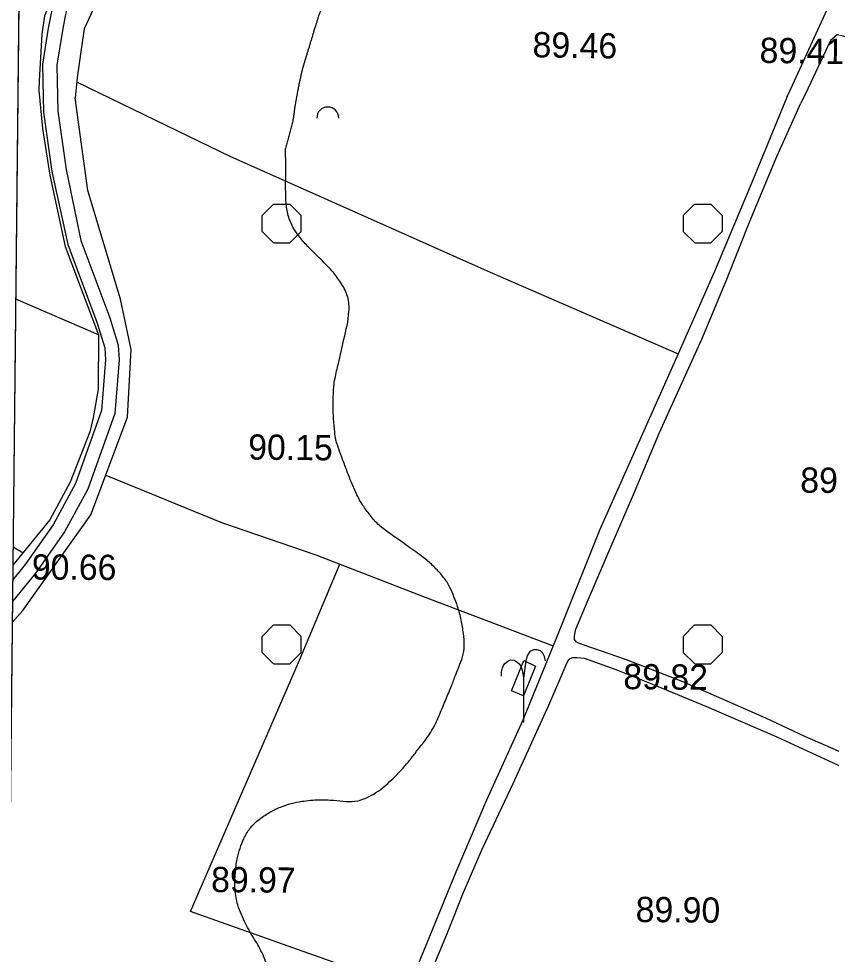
# Model space of a CAD drawing. Extents: x 417995 to 421451, y 4454518 to 4458015.
# Drawn here: x 419147.2 to 419340.2, y 4455617.9 to 4455840.2 of the extents above; entities that cross this region are included whole.
import ezdxf

# ---------------------------------------------------------------- set-up
doc = ezdxf.new("R2010")
doc.units = 0
for name, color, linetype in [('Egri_1m', 7, 'Continuous'), ('Hid_Havuz', 7, 'Continuous'), ('PAFTALAMA', 7, 'Continuous'), ('PL_KA_TARIM_ALANI', 7, 'Continuous'), ('S_Meyvalik', 7, 'Continuous'), ('Sinir_Duvar_tek_tarafa_ait', 7, 'Continuous'), ('Sinir_itirazli_Mulkiyet', 7, 'Continuous'), ('Sinir_Tel_bir_taraf', 7, 'Continuous'), ('TR_TARIMALANI', 7, 'Continuous'), ('Y_Kot_Noktasi', 7, 'Continuous'), ('Y_Lejant', 7, 'Continuous'), ('Y_Yol_Kotu', 7, 'Continuous'), ('Yol_Sose', 7, 'Continuous'), ('Yol_Toprak_Duz', 7, 'Continuous'), ('Yol_Toprak_Kesik', 7, 'Continuous')]:
    doc.layers.add(name, color=color, linetype=linetype)

msp = doc.modelspace()

# ---------------------------------------------------------------- linework, layer by layer
at = {"layer": 'Egri_1m'}
for points in [[(419266.78, 4455981.27), (419267.42, 4455981), (419268.7, 4455980.26), (419269.84, 4455979.15), (419271.04, 4455977.2), (419271.89, 4455975.31), (419272.51, 4455973.1), (419272.92, 4455970.46), (419273.07, 4455966.57), (419273.12, 4455960.67), (419273.1, 4455954.88), (419273.05, 4455949.5), (419272.97, 4455944.17), (419272.8, 4455940.5), (419272.47, 4455936.84), (419272.13, 4455934.62), (419271.58, 4455932.71), (419270.21, 4455929.62), (419268.24, 4455926.08), (419266.21, 4455923.01), (419264.28, 4455920.31), (419262.23, 4455917.43), (419259.91, 4455914.11), (419257.55, 4455910.82), (419255.12, 4455907.57), (419252.68, 4455904.32), (419250.66, 4455901.62), (419248.66, 4455898.95), (419245.71, 4455894.85), (419242.59, 4455890.24), (419240.4, 4455886.68), (419238.97, 4455883.75), (419237.74, 4455880.42), (419236.58, 4455876.62), (419235.26, 4455872.41), (419233.29, 4455866.97), (419231.01, 4455861.74), (419228.78, 4455857.75), (419226.38, 4455853.86), (419223.46, 4455849.44), (419220.52, 4455844.92), (419219.37, 4455843.07), (419218.99, 4455842.3), (419218.72, 4455841.65), (419218.52, 4455841.14), (419218.32, 4455840.54), (419218.09, 4455839.78), (419217.84, 4455838.99), (419217.54, 4455838), (419217.24, 4455837.02)], [(419217.24, 4455837.02), (419217.12, 4455836.62), (419216.99, 4455836.22), (419216.87, 4455835.83), (419216.75, 4455835.43), (419216.63, 4455835.03), (419216.51, 4455834.64), (419216.38, 4455834.24), (419216.26, 4455833.84), (419216.14, 4455833.44), (419216.02, 4455833.05), (419215.89, 4455832.65), (419215.77, 4455832.25), (419215.65, 4455831.85), (419215.53, 4455831.46), (419215.41, 4455831.06), (419215.28, 4455830.66), (419215.16, 4455830.27), (419215.04, 4455829.87), (419214.92, 4455829.47), (419214.82, 4455829.16), (419214.77, 4455828.96), (419214.72, 4455828.77), (419214.67, 4455828.58), (419214.62, 4455828.38), (419214.56, 4455828.19), (419214.51, 4455827.99), (419214.46, 4455827.8), (419214.41, 4455827.61), (419214.36, 4455827.41), (419214.31, 4455827.22), (419214.27, 4455827.02), (419214.23, 4455826.83), (419214.18, 4455826.63), (419214.14, 4455826.44), (419214.1, 4455826.24), (419214.06, 4455826.04), (419214.01, 4455825.85), (419213.97, 4455825.65), (419213.93, 4455825.46), (419213.91, 4455825.36), (419213.89, 4455825.3), (419213.88, 4455825.23), (419213.87, 4455825.17), (419213.85, 4455825.1), (419213.84, 4455825.03), (419213.83, 4455824.97), (419213.81, 4455824.9), (419213.8, 4455824.83), (419213.79, 4455824.77)], [(419213.79, 4455824.77), (419213.75, 4455824.58), (419213.71, 4455824.39), (419213.68, 4455824.21), (419213.64, 4455824.02), (419213.6, 4455823.83), (419213.57, 4455823.64), (419213.53, 4455823.46), (419213.49, 4455823.27), (419213.46, 4455823.08), (419213.42, 4455822.89), (419213.38, 4455822.69), (419213.32, 4455822.36), (419213.26, 4455822.03), (419213.2, 4455821.7), (419213.14, 4455821.37), (419213.08, 4455821.04), (419213.02, 4455820.71), (419212.96, 4455820.37), (419212.9, 4455820.04), (419212.84, 4455819.71), (419212.78, 4455819.38), (419212.73, 4455819.07), (419212.7, 4455818.84), (419212.67, 4455818.62), (419212.64, 4455818.39), (419212.62, 4455818.16), (419212.59, 4455817.93), (419212.56, 4455817.71), (419212.53, 4455817.48), (419212.5, 4455817.25), (419212.47, 4455817.02), (419212.45, 4455816.8), (419212.42, 4455816.59), (419212.38, 4455816.43), (419212.35, 4455816.28), (419212.32, 4455816.12), (419212.29, 4455815.96), (419212.26, 4455815.8), (419212.12, 4455815.26), (419211.96, 4455814.67), (419211.81, 4455814.07), (419211.66, 4455813.48), (419211.5, 4455812.89), (419211.35, 4455812.3), (419211.2, 4455811.7), (419211.04, 4455811.11), (419210.89, 4455810.52), (419210.74, 4455809.93), (419210.58, 4455809.34)], [(419244.73, 4455670.16), (419245.9, 4455672.13), (419247.18, 4455674.97), (419248.62, 4455678.37), (419249.98, 4455681.7), (419250.97, 4455684.25), (419251.74, 4455686.2), (419252.57, 4455688.55), (419253.01, 4455691.2), (419252.79, 4455694.14), (419252.28, 4455697.3), (419251.4, 4455700.53), (419250.55, 4455702.85), (419249.6, 4455705.05), (419248.11, 4455707.42), (419246.01, 4455709.76), (419243.82, 4455711.77), (419241.92, 4455713.18), (419238.31, 4455715.77), (419235.11, 4455718.04), (419232.5, 4455720.1), (419230.4, 4455722.53), (419228.72, 4455724.85), (419227.15, 4455727.82), (419225.94, 4455730.67), (419224.8, 4455733.62), (419223.71, 4455736.57), (419222.87, 4455738.93), (419222.54, 4455740.05), (419222.17, 4455742.75), (419221.93, 4455745.84), (419221.86, 4455748.94), (419221.95, 4455751.68), (419222.02, 4455752.71), (419222.32, 4455754.76), (419223.1, 4455758.24), (419224.41, 4455764), (419225.62, 4455770.61), (419225.34, 4455774.02), (419223.85, 4455777.19), (419221.92, 4455779.86), (419218.91, 4455783), (419215.78, 4455786.13), (419213.68, 4455788.57), (419211.43, 4455792.64), (419210.78, 4455795.75), (419210.61, 4455798.4), (419210.59, 4455801.07), (419210.6, 4455804.42), (419210.58, 4455809.34)], [(419243.78, 4455668.85), (419243.76, 4455668.82), (419243.74, 4455668.79), (419243.72, 4455668.77), (419243.7, 4455668.74), (419243.68, 4455668.72), (419243.66, 4455668.69), (419243.64, 4455668.66), (419243.62, 4455668.64), (419243.6, 4455668.61), (419243.58, 4455668.58), (419243.56, 4455668.56), (419243.54, 4455668.53), (419243.52, 4455668.5), (419243.5, 4455668.48), (419243.48, 4455668.45), (419243.46, 4455668.43), (419243.44, 4455668.4), (419243.42, 4455668.37), (419243.4, 4455668.35), (419243.38, 4455668.32), (419243.36, 4455668.29), (419243.34, 4455668.27), (419243.32, 4455668.24), (419243.3, 4455668.21), (419243.28, 4455668.19), (419243.26, 4455668.16), (419243.24, 4455668.14), (419243.22, 4455668.11), (419243.2, 4455668.08), (419243.18, 4455668.06), (419243.16, 4455668.03), (419243.14, 4455668), (419243.12, 4455667.98), (419243.1, 4455667.95), (419243.08, 4455667.92), (419243.06, 4455667.9), (419243.04, 4455667.87), (419243.02, 4455667.85), (419243, 4455667.82), (419242.98, 4455667.79), (419242.96, 4455667.77), (419242.94, 4455667.74), (419242.92, 4455667.71), (419242.9, 4455667.69), (419242.88, 4455667.66), (419242.86, 4455667.63), (419242.84, 4455667.61), (419242.82, 4455667.58), (419242.8, 4455667.56)], [(419243.78, 4455668.85), (419243.8, 4455668.87), (419243.82, 4455668.9), (419243.84, 4455668.93), (419243.86, 4455668.95), (419243.88, 4455668.98), (419243.9, 4455669.01), (419243.92, 4455669.03), (419243.93, 4455669.06), (419243.95, 4455669.09), (419243.97, 4455669.12), (419243.99, 4455669.14), (419244.01, 4455669.17), (419244.03, 4455669.2), (419244.05, 4455669.22), (419244.07, 4455669.25), (419244.09, 4455669.28), (419244.11, 4455669.3), (419244.13, 4455669.33), (419244.15, 4455669.36), (419244.17, 4455669.38), (419244.19, 4455669.41), (419244.21, 4455669.44), (419244.23, 4455669.46), (419244.25, 4455669.49), (419244.27, 4455669.52), (419244.28, 4455669.54), (419244.3, 4455669.57), (419244.32, 4455669.6), (419244.34, 4455669.62), (419244.36, 4455669.65), (419244.38, 4455669.68), (419244.4, 4455669.7), (419244.42, 4455669.73), (419244.44, 4455669.76), (419244.46, 4455669.78), (419244.48, 4455669.81), (419244.5, 4455669.84), (419244.52, 4455669.86), (419244.54, 4455669.89), (419244.56, 4455669.92), (419244.58, 4455669.95), (419244.6, 4455669.97), (419244.61, 4455670), (419244.63, 4455670.03), (419244.65, 4455670.05), (419244.67, 4455670.08), (419244.69, 4455670.11), (419244.71, 4455670.13), (419244.73, 4455670.16)], [(419230.59, 4455588.25), (419228.85, 4455588.77), (419226.6, 4455589.19), (419223.72, 4455589.67), (419220.1, 4455590.29), (419217.36, 4455591.45), (419215.16, 4455592.75), (419213.01, 4455594.48), (419210.83, 4455597.01), (419209.58, 4455599.31), (419208.45, 4455601.64), (419207.57, 4455603.92), (419207.07, 4455606.1), (419206.81, 4455608.27), (419206.68, 4455609.83), (419206.51, 4455611.6), (419206.24, 4455613.84), (419205.95, 4455615.6), (419205.22, 4455617.75), (419204.2, 4455619.72), (419203.21, 4455621.44), (419202.07, 4455623.33), (419201.08, 4455625.19), (419200.12, 4455627.31), (419199.23, 4455629.62), (419198.82, 4455631.4), (419198.58, 4455633.32), (419198.53, 4455635.21), (419198.65, 4455637.31), (419199.08, 4455640.53), (419199.75, 4455643.06), (419200.65, 4455645.39), (419202.04, 4455647.67), (419204.42, 4455650.03), (419206.87, 4455651.64), (419209.38, 4455652.86), (419211.93, 4455653.7), (419214.46, 4455654.23), (419218.57, 4455654.6), (419221.99, 4455654.47), (419224.86, 4455654.2), (419227.75, 4455654.38), (419230.41, 4455655.37), (419232.56, 4455656.64), (419234.36, 4455658.08), (419236.17, 4455659.76), (419238.03, 4455661.65), (419239.74, 4455663.63), (419241.31, 4455665.63), (419242.8, 4455667.56)]]:
    msp.add_spline(points, degree=3, dxfattribs=at)
at = {"layer": 'Hid_Havuz'}
for points in [[(419272.32, 4455687.59), (419272.07, 4455688.64), (419271.69, 4455689.41), (419271.13, 4455689.97), (419270.25, 4455690.21), (419269.41, 4455690.21), (419268.61, 4455689.83), (419268.05, 4455688.99), (419267.59, 4455687.66), (419267.07, 4455683.46)], [(419261.82, 4455683.95), (419261.85, 4455684.96), (419262.06, 4455685.91), (419262.34, 4455686.5), (419262.66, 4455686.96), (419263.32, 4455687.52), (419264.02, 4455687.83), (419264.76, 4455687.73), (419265.46, 4455687.41), (419266.02, 4455686.89), (419266.47, 4455686.33), (419266.75, 4455685.42), (419266.89, 4455684.61), (419267.07, 4455683.46), (419267.07, 4455672.96)]]:
    msp.add_lwpolyline(points, dxfattribs=at)
msp.add_lwpolyline([(419269.92, 4455686.32), (419267.03, 4455679.33), (419264.2, 4455680.5), (419267.13, 4455687.68)], close=True, dxfattribs=at)
at = {"layer": 'PAFTALAMA'}
msp.add_line((419168.18, 4457798.01), (419138.44, 4455021.89), dxfattribs=at)
at = {"layer": 'PL_KA_TARIM_ALANI'}
msp.add_line((419159.16, 4456956.55), (419138.44, 4455021.89), dxfattribs=at)
at = {"layer": 'S_Meyvalik'}
msp.add_arc((419220.6, 4455816.56), 2.62, 360, 180, dxfattribs=at)
at = {"layer": 'Sinir_Duvar_tek_tarafa_ait'}
msp.add_lwpolyline([(419166.13, 4455765.04), (419166.03, 4455752.18), (419164.86, 4455745.35), (419164.11, 4455741.99), (419159.41, 4455730.02), (419154.59, 4455721.07), (419145.82, 4455710.3)], dxfattribs=at)
at = {"layer": 'Sinir_itirazli_Mulkiyet'}
for points in [[(419185.55, 4455873.78), (419183.02, 4455870.77), (419178.94, 4455868.98), (419172.57, 4455864.73), (419163.5, 4455858.62), (419159.39, 4455853.74), (419157.55, 4455850.4), (419155.87, 4455846.77), (419153.36, 4455840.84), (419152.67, 4455836.5), (419152.09, 4455825.43)], [(419185.41, 4455861.33), (419180.51, 4455859.96), (419175.65, 4455856.81), (419172.69, 4455854.21), (419170.88, 4455852.25), (419167.73, 4455848.09), (419166.35, 4455845.68), (419162.71, 4455837.76), (419162.1, 4455833.39), (419161.06, 4455826.23), (419160.98, 4455825.33)], [(419152.09, 4455825.43), (419151.97, 4455823.12), (419152.85, 4455814.08)], [(419160.98, 4455825.33), (419160.61, 4455821.33)], [(419160.96, 4455825.15), (419184.9, 4455813.55)], [(419152.85, 4455814.08), (419154.58, 4455803.01), (419158.25, 4455786.03), (419166.13, 4455765.04)], [(419184.9, 4455813.55), (419184.9, 4455813.55)], [(419184.9, 4455813.55), (419197.33, 4455807.53), (419259.15, 4455779.97), (419303.8, 4455760.56)], [(419166.13, 4455765.04), (419146.49, 4455773.57)], [(419167.88, 4455731.7), (419183.95, 4455725.14)], [(419183.95, 4455725.14), (419183.96, 4455725.14)], [(419183.96, 4455725.14), (419195.32, 4455720.5)], [(419195.32, 4455720.5), (419217.75, 4455712.76), (419243.08, 4455702.99), (419274.13, 4455691.18)], [(419145.86, 4455714.66), (419148.25, 4455713.29)], [(419239.76, 4455609.7), (419204.96, 4455622.04), (419188, 4455628.04), (419213.84, 4455687.73), (419223.45, 4455710.57)]]:
    msp.add_lwpolyline(points, dxfattribs=at)
at = {"layer": 'Sinir_Tel_bir_taraf'}
msp.add_lwpolyline([(419145.67, 4455696.73), (419148.2, 4455699.53), (419164.36, 4455722.29), (419173.04, 4455745.51), (419173.93, 4455761.56), (419171.37, 4455773.52), (419163.61, 4455799.35), (419160.61, 4455821.33)], dxfattribs=at)
at = {"layer": 'TR_TARIMALANI'}
for p, q in [((419205.01, 4455793.42), (419207.71, 4455796.13)), ((419207.75, 4455796.14), (419211.58, 4455796.14)), ((419214.26, 4455793.42), (419211.55, 4455796.13)), ((419305.01, 4455793.42), (419307.71, 4455796.13)), ((419307.75, 4455796.14), (419311.58, 4455796.14)), ((419314.26, 4455793.42), (419311.55, 4455796.13)), ((419205.04, 4455789.6), (419205.04, 4455793.43)), ((419214.29, 4455789.6), (419214.29, 4455793.43)), ((419305.04, 4455789.6), (419305.04, 4455793.43)), ((419314.29, 4455789.6), (419314.29, 4455793.43)), ((419207.72, 4455786.88), (419205.01, 4455789.59)), ((419211.55, 4455786.88), (419214.25, 4455789.59)), ((419307.72, 4455786.88), (419305.01, 4455789.59)), ((419311.55, 4455786.88), (419314.25, 4455789.59)), ((419207.75, 4455786.89), (419211.58, 4455786.89)), ((419307.75, 4455786.89), (419311.58, 4455786.89)), ((419205.01, 4455693.42), (419207.71, 4455696.13)), ((419207.75, 4455696.14), (419211.58, 4455696.14)), ((419214.26, 4455693.42), (419211.55, 4455696.13)), ((419305.01, 4455693.42), (419307.71, 4455696.13)), ((419307.75, 4455696.14), (419311.58, 4455696.14)), ((419314.26, 4455693.42), (419311.55, 4455696.13)), ((419205.04, 4455689.6), (419205.04, 4455693.43)), ((419214.29, 4455689.6), (419214.29, 4455693.43)), ((419305.04, 4455689.6), (419305.04, 4455693.43)), ((419314.29, 4455689.6), (419314.29, 4455693.43)), ((419207.72, 4455686.88), (419205.01, 4455689.59)), ((419211.55, 4455686.88), (419214.25, 4455689.59)), ((419307.72, 4455686.88), (419305.01, 4455689.59)), ((419311.55, 4455686.88), (419314.25, 4455689.59)), ((419207.75, 4455686.89), (419211.58, 4455686.89)), ((419307.75, 4455686.89), (419311.58, 4455686.89))]:
    msp.add_line(p, q, dxfattribs=at)
at = {"layer": 'Y_Lejant'}
msp.add_lwpolyline([(419168.18, 4457798.01), (421295.36, 4457775.52), (421266.41, 4454999.4), (419138.44, 4455021.89)], close=True, dxfattribs=at)
at = {"layer": 'Yol_Sose'}
for points in [[(419185.49, 4455868.78), (419178.76, 4455866.17), (419170.32, 4455860.85), (419164.09, 4455855.96), (419160.48, 4455851.8), (419158.23, 4455848.57), (419156.03, 4455844.97), (419155.28, 4455843.33), (419154.8, 4455841.07), (419154.22, 4455837.91), (419152.85, 4455829.38), (419152.93, 4455825.42)], [(419185.45, 4455865.09), (419180.31, 4455863.09), (419172.3, 4455858.05), (419166.47, 4455853.47), (419163.19, 4455849.69), (419161.1, 4455846.69), (419159.06, 4455843.36), (419158.55, 4455842.24), (419158.16, 4455840.41), (419157.6, 4455837.33), (419156.28, 4455829.14), (419156.36, 4455825.38)], [(419152.93, 4455825.42), (419153.07, 4455817.93), (419155.08, 4455803.9)], [(419156.36, 4455825.38), (419156.5, 4455818.21), (419158.47, 4455804.38)], [(419158.47, 4455804.38), (419161.96, 4455787.46), (419168.83, 4455769.1), (419170.85, 4455762.58), (419171.03, 4455759.1), (419170.05, 4455746.4), (419163.65, 4455728.41), (419158.11, 4455718.23), (419151.3, 4455708.54), (419145.72, 4455701.73)], [(419155.08, 4455803.9), (419158.87, 4455786.55), (419165.79, 4455768.06), (419167.66, 4455762.01), (419167.82, 4455759.14), (419166.89, 4455747.07), (419160.71, 4455729.73), (419155.38, 4455719.92), (419148.75, 4455710.48), (419145.78, 4455706.86)]]:
    msp.add_lwpolyline(points, dxfattribs=at)
at = {"layer": 'Yol_Toprak_Duz'}
for points in [[(419345.9, 4455834.99), (419343.21, 4455835.95), (419341.87, 4455836.35), (419341.54, 4455836.36), (419339.95, 4455834.98), (419334.55, 4455823.48)], [(419334.55, 4455823.48), (419332.96, 4455820.09)], [(419279.17, 4455693.1), (419279.14, 4455693.55), (419279.53, 4455695.11), (419282.44, 4455702.08), (419287.89, 4455714.83), (419293.2, 4455727.12), (419299.33, 4455741.85), (419309.38, 4455764.02), (419315.2, 4455777.86), (419321.08, 4455792.62), (419327.26, 4455807.4), (419332.96, 4455820.09)], [(419244.63, 4455612.57), (419249.14, 4455623.39), (419252.77, 4455632.39), (419257.27, 4455642.88), (419264.63, 4455658.44), (419273.08, 4455677.11), (419277.46, 4455687.18), (419277.84, 4455687.88), (419278.15, 4455688.2), (419278.81, 4455688.39), (419279.9, 4455688.43), (419281.46, 4455688.22), (419283.08, 4455687.69), (419288.97, 4455685.52), (419297.69, 4455682.04), (419310.49, 4455676.75), (419327.25, 4455669.58), (419342.69, 4455662.42), (419360.53, 4455655.08), (419380.23, 4455647.48), (419447.58, 4455619.76)]]:
    msp.add_lwpolyline(points, dxfattribs=at)
at = {"layer": 'Yol_Toprak_Kesik'}
for points in [[(419330.53, 4455823.52), (419339.6, 4455843.25)], [(419329.7, 4455821.71), (419320.86, 4455800.3), (419312.41, 4455780.1), (419303.49, 4455759.87), (419285.22, 4455718.78), (419275, 4455693.29), (419266.89, 4455673.52), (419258.25, 4455654.54), (419250.98, 4455637.39), (419242.62, 4455616.86), (419237.65, 4455604.42), (419232.69, 4455593.4), (419227.45, 4455580.53), (419223.55, 4455570.92), (419218.55, 4455560.61), (419215.9, 4455553.83), (419211.86, 4455544.35), (419201.77, 4455521.61)], [(419329.7, 4455821.71), (419330.53, 4455823.52)], [(419448.58, 4455621.89), (419439.29, 4455625.86), (419422.67, 4455632.32), (419406.03, 4455639.56), (419391.42, 4455645.86), (419375.45, 4455652.67), (419360.54, 4455658.63), (419346.74, 4455664), (419333.88, 4455669.65), (419324.62, 4455673.97), (419315.42, 4455677.99), (419304.72, 4455682.68), (419291.49, 4455687.81), (419281.23, 4455691.4), (419280.57, 4455691.61), (419280.09, 4455691.78), (419279.6, 4455692.12), (419279.2, 4455692.65), (419279.17, 4455693.1)]]:
    msp.add_lwpolyline(points, dxfattribs=at)

# ---------------------------------------------------------------- texts
at = {"layer": 'Y_Kot_Noktasi'}
for s, rotation, p in [('89.46', 359.0723, (419269.19, 4455831.02)), ('90.15', 359.4709, (419201.68, 4455735.42)), ('89.60', 359.4709, (419332.77, 4455727.57)), ('90.66', 359.6252, (419150.31, 4455706.93)), ('89.97', 359.4709, (419192.87, 4455632.68)), ('89.90', 359.4709, (419293.68, 4455625.56))]:
    msp.add_text(s, height=6, rotation=rotation, dxfattribs=at).set_placement(p)
at = {"layer": 'Y_Yol_Kotu'}
for s, rotation, p in [('89.41', 359.0723, (419323.1, 4455829.69)), ('89.82', 359.4709, (419290.76, 4455680.89))]:
    msp.add_text(s, height=6, rotation=rotation, dxfattribs=at).set_placement(p)

doc.saveas('drawing.dxf')
